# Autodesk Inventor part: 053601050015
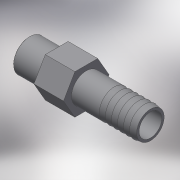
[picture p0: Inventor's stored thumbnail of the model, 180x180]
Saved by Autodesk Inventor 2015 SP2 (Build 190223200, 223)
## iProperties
Created: 2017-10
Part Number: 053601050015
Material: Generic
Description: PLASSON THREADED HOSE NOZZLE 1.1/2"-50
Document SubType Name: Modeling
Designer: KIM
Density: 1 g/cm^3
Appearance: Default
Author: KIM
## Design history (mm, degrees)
derived "053601.ipt"
feature "Solid1::053601.ipt"
tag "TaggingFeature1"
body "Solid1"
other parameters: "d0" = 94, "d1" = 170 deg, "d6" = 33.4621, "d8" = 28.2, "d9" = 47.803, "d11" = 22, "d12" = 16, "d13" = 16, "d14" = 0, "d15" = 0.12, "d_" = 12, "H_" = 94, "R_" = 47.803, "B_" = 16, "Lt_" = 22
